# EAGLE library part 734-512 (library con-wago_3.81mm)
Serie 734, Federleiste mit geraden Einlötstiften / Series 734, Female connector with straight solder pins Polzahl / Pole No.: 12 Bemessungsspannung / Rated Voltage: 160 V Nennstrom / Nominal Current: 10 A Lötstiftlänge: / Solder Pin Length: 3.8 mm Farbe / Color: orange / orange Stand: 01.01.2012. Die jeweils aktuellen Daten zu diesem Artikel finden Sie in unserem Produktkatalog, den Sie unter www.wago.com einsehen können. As of: 01/01/2012. Please find the newest data for this article in our product catalogue, which can be viewed under www.wago.com.
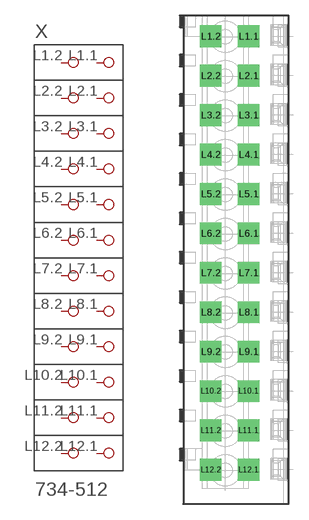
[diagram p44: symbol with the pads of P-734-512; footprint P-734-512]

Designator prefix X

## 734-512  [P-734-512]
L1.1  P1.1
L1.2  P1.2
L2.1  P2.1
L2.2  P2.2
L3.1  P3.1
L3.2  P3.2
L4.1  P4.1
L4.2  P4.2
L5.1  P5.1
L5.2  P5.2
L6.1  P6.1
L6.2  P6.2
L7.1  P7.1
L7.2  P7.2
L8.1  P8.1
L8.2  P8.2
L9.1  P9.1
L9.2  P9.2
L10.1  P10.1
L10.2  P10.2
L11.1  P11.1
L11.2  P11.2
L12.1  P12.1
L12.2  P12.2

## Footprint P-734-512 (pad centres in mm)
drill 1.4 square: L1.1 1.152,21.6; L1.2 -2.498,21.6; L2.1 1.152,17.79; L2.2 -2.498,17.79; L3.1 1.152,13.98; L3.2 -2.498,13.98; L4.1 1.152,10.17; L4.2 -2.498,10.17; L5.1 1.152,6.36; L5.2 -2.498,6.36; L6.1 1.152,2.55; L6.2 -2.498,2.55; L7.1 1.152,-1.26; L7.2 -2.498,-1.26; L8.1 1.152,-5.07; L8.2 -2.498,-5.07; L9.1 1.152,-8.88; L9.2 -2.498,-8.88; L10.1 1.152,-12.69; L10.2 -2.498,-12.69; L11.1 1.152,-16.5; L11.2 -2.498,-16.5; L12.1 1.152,-20.31; L12.2 -2.498,-20.31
